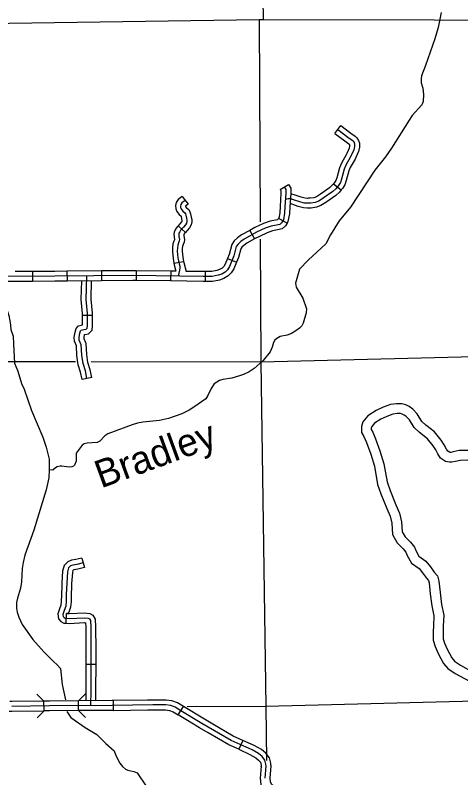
# Model space of a CAD drawing. Extents: x 1373862 to 1376999, y 1168398 to 1170455.
# Drawn here: x 1375274.1 to 1375410.3, y 1169193.7 to 1169426.9 of the extents above; entities that cross this region are included whole.
import ezdxf

# ---------------------------------------------------------------- set-up
doc = ezdxf.new("R2010")
doc.units = 0
for name, color, linetype in [('Level 31', 7, 'Continuous'), ('Level 32', 7, 'Continuous'), ('Level 35', 7, 'Continuous'), ('Level 38', 7, 'Continuous'), ('Level 4', 7, 'Continuous'), ('Level 45', 7, 'Continuous'), ('Level 46', 7, 'Continuous'), ('Level 5', 7, 'Continuous'), ('Level 8', 7, 'Continuous')]:
    doc.layers.add(name, color=color, linetype=linetype)

msp = doc.modelspace()

# ---------------------------------------------------------------- linework, layer by layer
at = {"layer": 'Level 31'}
for p, q in [((1375282.94, 1169214.11), (1375282.9, 1169217.11)), ((1375304.02, 1169217.24), (1375304.06, 1169214.24)), ((1375314.58, 1169217.38), (1375314.58, 1169217.38)), ((1375323.97, 1169212.86), (1375325.52, 1169215.43)), ((1375343.71, 1169205.08), (1375342.47, 1169202.35)), ((1375352.29, 1169197.61), (1375352.29, 1169197.61))]:
    msp.add_line(p, q, dxfattribs=at)
for points in [[(1375282.9, 1169217.11), (1375273.12, 1169216.99), (1375272.43, 1169217.02)], [(1375293.49, 1169214.18), (1375293.47, 1169217.18), (1375284.59, 1169217.13), (1375282.9, 1169217.11)], [(1375304.02, 1169217.24), (1375303.79, 1169217.24), (1375293.47, 1169217.18)], [(1375314.58, 1169217.38), (1375304.02, 1169217.24)], [(1375325.52, 1169215.43), (1375325.51, 1169215.44), (1375323.71, 1169216.55), (1375322.04, 1169217.2), (1375320.29, 1169217.43), (1375316.17, 1169217.41), (1375314.58, 1169217.38)], [(1375350.51, 1169193.53), (1375350.83, 1169197.25), (1375350.74, 1169197.79), (1375350.43, 1169199.06), (1375349.61, 1169200.13), (1375348.51, 1169201.03), (1375346.51, 1169202.16), (1375340.11, 1169205.07), (1375331.19, 1169210.26), (1375324.73, 1169214.16), (1375323.04, 1169215.2), (1375321.66, 1169215.74), (1375320.19, 1169215.93), (1375316.19, 1169215.91), (1375303.8, 1169215.74), (1375284.6, 1169215.63), (1375273.09, 1169215.49)], [(1375304.06, 1169214.24), (1375303.82, 1169214.24), (1375293.49, 1169214.18)], [(1375304.06, 1169214.24), (1375314.62, 1169214.38)], [(1375314.62, 1169214.38), (1375316.2, 1169214.41), (1375320.1, 1169214.43), (1375321.28, 1169214.27), (1375322.37, 1169213.85), (1375323.95, 1169212.88), (1375323.97, 1169212.86)], [(1375334.57, 1169210.03), (1375331.96, 1169211.55), (1375325.52, 1169215.43)], [(1375272.29, 1169214.03), (1375273.07, 1169213.99), (1375282.94, 1169214.11)], [(1375293.49, 1169214.18), (1375284.61, 1169214.13), (1375282.94, 1169214.11)], [(1375333.06, 1169207.44), (1375330.43, 1169208.97), (1375323.97, 1169212.86)], [(1375343.71, 1169205.08), (1375340.79, 1169206.4), (1375334.57, 1169210.03)], [(1375342.47, 1169202.35), (1375339.42, 1169203.74), (1375333.06, 1169207.44)], [(1375352.29, 1169197.61), (1375352.21, 1169198.09), (1375351.81, 1169199.72), (1375350.7, 1169201.18), (1375349.36, 1169202.28), (1375347.19, 1169203.5), (1375343.71, 1169205.08)], [(1375342.47, 1169202.35), (1375345.83, 1169200.82), (1375347.66, 1169199.79), (1375348.52, 1169199.08), (1375349.05, 1169198.4), (1375349.27, 1169197.49), (1375349.33, 1169197.13)], [(1375349.33, 1169197.13), (1375349.32, 1169197.19), (1375349.01, 1169193.51), (1375349.22, 1169191.61), (1375349.88, 1169190.13), (1375350.79, 1169189.05), (1375352.54, 1169187.97), (1375354.46, 1169187.8)], [(1375354.73, 1169190.79), (1375353.51, 1169190.9), (1375352.77, 1169191.35), (1375352.44, 1169191.74), (1375352.15, 1169192.4), (1375352.02, 1169193.55), (1375352.34, 1169197.31), (1375352.29, 1169197.61)]]:
    msp.add_lwpolyline(points, dxfattribs=at)
at = {"layer": 'Level 32'}
for p, q in [((1375355.06, 1169373.58), (1375357.62, 1169375.15)), ((1375325.16, 1169371.45), (1375326.96, 1169369.05)), ((1375354.62, 1169364.78), (1375357.22, 1169363.29)), ((1375323.88, 1169362.46), (1375326.12, 1169360.46)), ((1375345.82, 1169361.06), (1375347.27, 1169358.44)), ((1375338.98, 1169352.45), (1375341.77, 1169351.36)), ((1375322.65, 1169351.01), (1375325.59, 1169351.57)), ((1375279.39, 1169348.48), (1375279.4, 1169345.48)), ((1375289.94, 1169348.55), (1375289.97, 1169345.56)), ((1375300.5, 1169348.65), (1375300.53, 1169345.65)), ((1375311.09, 1169348.73), (1375311.06, 1169345.73)), ((1375321.65, 1169348.6), (1375321.62, 1169345.6)), ((1375332.19, 1169348.48), (1375332.19, 1169345.48))]:
    msp.add_line(p, q, dxfattribs=at)
for points in [[(1375357.62, 1169375.15), (1375358.33, 1169374), (1375358.33, 1169372.39), (1375358.06, 1169368.23), (1375357.97, 1169366.11), (1375357.5, 1169363.78), (1375357.22, 1169363.29)], [(1375356.34, 1169374.37), (1375356.83, 1169373.58), (1375356.83, 1169372.43), (1375356.56, 1169368.31), (1375356.47, 1169366.29), (1375356.08, 1169364.31), (1375355.55, 1169363.39), (1375354.98, 1169362.91), (1375353.97, 1169362.69), (1375352.39, 1169362.38), (1375350.55, 1169361.77), (1375348.05, 1169360.58), (1375344.1, 1169358.39), (1375343.05, 1169357.64), (1375342.22, 1169356.9), (1375341.69, 1169356.11), (1375340.9, 1169353.25), (1375339.63, 1169350.01), (1375339.01, 1169349.04), (1375338.27, 1169348.34), (1375337.26, 1169347.72), (1375336.16, 1169347.33), (1375334.32, 1169346.98), (1375331.56, 1169346.98), (1375310.1, 1169347.24), (1375286.24, 1169347.02), (1375271.54, 1169346.93)], [(1375355.06, 1169373.58), (1375355.33, 1169373.15), (1375355.33, 1169372.48), (1375355.06, 1169368.39), (1375354.98, 1169366.47), (1375354.66, 1169364.85), (1375354.62, 1169364.78)], [(1375325.16, 1169371.45), (1375323.92, 1169370.52), (1375323.29, 1169369.62), (1375323.1, 1169368.64), (1375323.21, 1169367.68), (1375323.54, 1169366.88), (1375324.21, 1169365.97), (1375324.8, 1169365.46), (1375324.82, 1169365.41), (1375324.96, 1169364.57), (1375325.07, 1169364.08), (1375325.07, 1169363.91), (1375325.05, 1169363.8), (1375324.97, 1169363.65), (1375324.43, 1169363.08), (1375323.88, 1169362.46)], [(1375326.06, 1169370.25), (1375325.01, 1169369.46), (1375324.7, 1169369.02), (1375324.61, 1169368.58), (1375324.68, 1169368.06), (1375324.85, 1169367.62), (1375325.32, 1169367), (1375325.97, 1169366.43), (1375326.17, 1169366.1), (1375326.28, 1169365.77), (1375326.43, 1169364.85), (1375326.57, 1169364.24), (1375326.57, 1169363.78), (1375326.48, 1169363.29), (1375326.19, 1169362.77), (1375325.53, 1169362.07), (1375324.77, 1169361.2), (1375324.39, 1169360.65), (1375324.17, 1169360.19), (1375324.15, 1169359.8), (1375324.17, 1169359.23), (1375324.31, 1169358.28), (1375324.26, 1169357.84), (1375324.04, 1169357.23), (1375323.78, 1169356.55), (1375323.69, 1169355.78), (1375323.67, 1169354.71), (1375323.85, 1169352.71), (1375324.2, 1169350.89), (1375324.39, 1169350.13), (1375324.44, 1169349.6), (1375324.35, 1169348.92), (1375323.96, 1169347.07)], [(1375326.96, 1169369.05), (1375326.14, 1169368.44), (1375326.14, 1169368.43), (1375326.17, 1169368.36), (1375326.42, 1169368.03), (1375327.14, 1169367.41), (1375327.54, 1169366.73), (1375327.74, 1169366.14), (1375327.91, 1169365.13), (1375328.07, 1169364.4), (1375328.07, 1169363.64), (1375327.91, 1169362.79), (1375327.42, 1169361.88), (1375326.64, 1169361.05), (1375326.12, 1169360.46)], [(1375354.62, 1169364.78), (1375354.38, 1169364.37), (1375354.3, 1169364.3), (1375353.67, 1169364.16), (1375352.01, 1169363.84), (1375349.99, 1169363.16), (1375347.37, 1169361.92), (1375345.82, 1169361.06)], [(1375323.88, 1169362.46), (1375323.58, 1169362.13), (1375323.09, 1169361.4), (1375322.69, 1169360.57), (1375322.65, 1169359.81), (1375322.68, 1169359.09), (1375322.8, 1169358.25), (1375322.79, 1169358.18), (1375322.64, 1169357.75), (1375322.31, 1169356.91), (1375322.19, 1169355.88), (1375322.17, 1169354.66), (1375322.36, 1169352.5), (1375322.65, 1169351.01)], [(1375357.22, 1169363.29), (1375356.72, 1169362.42), (1375355.67, 1169361.52), (1375354.28, 1169361.22), (1375352.78, 1169360.93), (1375351.11, 1169360.37), (1375348.74, 1169359.25), (1375347.27, 1169358.44)], [(1375326.12, 1169360.46), (1375325.95, 1169360.28), (1375325.7, 1169359.91), (1375325.66, 1169359.82), (1375325.65, 1169359.79), (1375325.67, 1169359.36), (1375325.82, 1169358.31), (1375325.74, 1169357.51), (1375325.45, 1169356.71), (1375325.25, 1169356.19), (1375325.19, 1169355.68), (1375325.17, 1169354.76), (1375325.33, 1169352.92), (1375325.59, 1169351.57)], [(1375345.82, 1169361.06), (1375343.3, 1169359.66), (1375342.11, 1169358.82), (1375341.07, 1169357.89), (1375340.31, 1169356.74), (1375339.48, 1169353.73), (1375338.98, 1169352.45)], [(1375347.27, 1169358.44), (1375344.9, 1169357.12), (1375343.99, 1169356.47), (1375343.36, 1169355.91), (1375343.07, 1169355.47), (1375342.33, 1169352.78), (1375341.77, 1169351.36)], [(1375338.98, 1169352.45), (1375338.28, 1169350.69), (1375337.85, 1169350), (1375337.35, 1169349.54), (1375336.61, 1169349.08), (1375335.77, 1169348.78), (1375334.18, 1169348.48), (1375332.19, 1169348.48)], [(1375322.65, 1169351.01), (1375322.73, 1169350.56), (1375323.25, 1169348.58)], [(1375325.59, 1169351.57), (1375325.66, 1169351.22), (1375326.35, 1169348.54)], [(1375341.77, 1169351.36), (1375340.97, 1169349.32), (1375340.18, 1169348.08), (1375339.18, 1169347.14), (1375337.91, 1169346.36), (1375336.56, 1169345.88), (1375334.46, 1169345.48), (1375332.19, 1169345.48)], [(1375279.39, 1169348.48), (1375274.13, 1169348.45)], [(1375289.94, 1169348.55), (1375286.23, 1169348.52), (1375279.39, 1169348.48)], [(1375300.5, 1169348.65), (1375289.94, 1169348.55)], [(1375311.09, 1169348.73), (1375310.11, 1169348.74), (1375300.5, 1169348.65)], [(1375321.65, 1169348.6), (1375311.09, 1169348.73)], [(1375323.25, 1169348.58), (1375321.65, 1169348.6)], [(1375332.19, 1169348.48), (1375331.57, 1169348.48), (1375326.35, 1169348.54)], [(1375279.4, 1169345.48), (1375271.57, 1169345.43), (1375268.88, 1169345.35)], [(1375289.97, 1169345.56), (1375286.25, 1169345.52), (1375279.4, 1169345.48)], [(1375300.53, 1169345.65), (1375289.97, 1169345.56)], [(1375311.06, 1169345.73), (1375310.1, 1169345.74), (1375300.53, 1169345.65)], [(1375321.62, 1169345.6), (1375311.06, 1169345.73)], [(1375332.19, 1169345.48), (1375331.55, 1169345.48), (1375321.62, 1169345.6)]]:
    msp.add_lwpolyline(points, dxfattribs=at)
at = {"layer": 'Level 35'}
for points in [[(1375404.32, 1169427.73), (1375403.4, 1169423.15), (1375402.39, 1169419.65), (1375399.52, 1169411.53), (1375398.31, 1169408.37), (1375398.19, 1169407.44), (1375398.26, 1169406.24), (1375398.67, 1169404.55), (1375398.88, 1169402.59), (1375398.81, 1169400.5), (1375398.4, 1169399.52), (1375395.49, 1169396.16), (1375394.5, 1169394.75), (1375389.16, 1169386.24), (1375387.29, 1169383.56), (1375384.04, 1169379.52), (1375376.57, 1169368.14), (1375373.1, 1169364), (1375370.53, 1169359.72), (1375369.03, 1169356.97), (1375363.66, 1169351.93), (1375361.03, 1169349.25), (1375359.78, 1169344.9), (1375360.05, 1169343.67), (1375362.04, 1169340.35), (1375363.14, 1169337.09), (1375363.1, 1169335.83), (1375362.12, 1169332.69), (1375361.7, 1169331.88), (1375361.04, 1169331.16), (1375359.94, 1169330.3), (1375358.62, 1169329.53), (1375357.27, 1169329.07), (1375355.12, 1169328.57), (1375354.06, 1169327.98), (1375353.45, 1169327.48), (1375353.07, 1169326.81), (1375352.63, 1169325.31), (1375352.09, 1169323.89)], [(1375268.34, 1169343.59), (1375269.9, 1169341), (1375271.11, 1169338.04), (1375272.15, 1169335.06), (1375272.44, 1169333.45), (1375272.63, 1169332.04), (1375272.76, 1169330.71), (1375273.44, 1169328.67), (1375273.63, 1169326.29), (1375273.94, 1169320.49), (1375274.94, 1169318), (1375276.07, 1169314.23)], [(1375352.09, 1169323.89), (1375349.93, 1169321.27), (1375347.12, 1169318.83), (1375345.64, 1169317.84), (1375343.93, 1169317.02), (1375342.68, 1169316.56), (1375340.29, 1169315.89), (1375337.62, 1169315.48), (1375336.57, 1169315.15), (1375334.94, 1169314.09), (1375333.98, 1169312.72), (1375332.95, 1169310.52), (1375332.4, 1169309.56), (1375328.67, 1169306.96), (1375327.31, 1169306.12), (1375325.04, 1169304.93), (1375320.97, 1169303.52), (1375318.23, 1169302.97), (1375313.14, 1169302.39), (1375311.45, 1169302.06), (1375309.84, 1169301.62), (1375302.47, 1169298.87), (1375301.49, 1169298.2), (1375299.99, 1169296.6), (1375299.12, 1169296.21), (1375296.07, 1169296.03), (1375295.17, 1169295.81), (1375294.6, 1169295.41), (1375292.79, 1169292.96), (1375292.71, 1169290.49), (1375292.24, 1169289.23), (1375291.91, 1169288.98), (1375291.42, 1169288.73), (1375290.6, 1169288.62), (1375288.41, 1169288.93), (1375287.83, 1169288.91), (1375286.94, 1169288.71), (1375286.44, 1169288.45), (1375285.64, 1169287.69), (1375284.54, 1169287.88)], [(1375276.07, 1169314.23), (1375276.83, 1169312.55), (1375279.09, 1169305.95), (1375282.52, 1169297.84), (1375283.6, 1169294.78), (1375284.46, 1169291.07), (1375284.54, 1169287.88), (1375284.42, 1169285.37), (1375283.6, 1169281.68), (1375279.82, 1169269.34), (1375277.08, 1169261.7), (1375276.56, 1169259.5), (1375276.29, 1169257.61), (1375276.01, 1169253.55), (1375275.74, 1169251.65), (1375274.86, 1169248.6), (1375274.56, 1169247.21), (1375274.52, 1169245.54), (1375274.76, 1169244.28), (1375275.2, 1169242.75), (1375276.21, 1169240.55), (1375279.51, 1169235.95), (1375282.83, 1169232.22), (1375285.81, 1169229.23), (1375286.96, 1169228.24), (1375287.93, 1169227.1), (1375288.42, 1169222.15), (1375289.52, 1169217.47)], [(1375289.87, 1169213.89), (1375291.09, 1169212.12), (1375295.47, 1169209.01), (1375299.06, 1169206.85), (1375301.79, 1169204.15), (1375304.41, 1169201.87)], [(1375304.41, 1169201.87), (1375304.78, 1169200.75), (1375305.29, 1169199.64), (1375306.14, 1169198.09), (1375306.91, 1169197.08), (1375307.84, 1169196.31), (1375308.55, 1169195.98), (1375310.39, 1169195.59), (1375311.42, 1169195.16), (1375314.12, 1169191.13), (1375314.2, 1169189.37), (1375314.12, 1169188.15), (1375314.27, 1169186.17), (1375314.52, 1169184.51), (1375315.66, 1169180.56), (1375316.04, 1169179.76)]]:
    msp.add_lwpolyline(points, dxfattribs=at)
at = {"layer": 'Level 38'}
for points in [[(1375280.75, 1169219.2), (1375282.9, 1169217.11)], [(1375293.47, 1169217.18), (1375295.58, 1169219.31)], [(1375282.94, 1169214.11), (1375280.84, 1169211.96)], [(1375295.62, 1169212.07), (1375293.49, 1169214.18)]]:
    msp.add_lwpolyline(points, dxfattribs=at)
at = {"layer": 'Level 4'}
msp.add_lwpolyline([(1375141.28, 1169422.97), (1375218.46, 1169423.68), (1375243.37, 1169424.03), (1375244.34, 1169424.04), (1375348.71, 1169425.54), (1375349.94, 1169425.54), (1375454.46, 1169425.4), (1375455.43, 1169425.4), (1375476.41, 1169425.48)], dxfattribs=at)
at = {"layer": 'Level 45'}
for p, q in [((1375371.82, 1169390.71), (1375373.61, 1169393.12)), ((1375371.44, 1169375.34), (1375373.78, 1169373.47)), ((1375297.7, 1169335.02), (1375294.7, 1169335.02)), ((1375297.49, 1169316.03), (1375294.55, 1169315.47)), ((1375294.47, 1169260.85), (1375295.28, 1169257.97)), ((1375289.69, 1169240.91), (1375289.8, 1169243.91)), ((1375295.72, 1169228.37), (1375298.72, 1169228.36))]:
    msp.add_line(p, q, dxfattribs=at)
for points in [[(1375372.72, 1169391.91), (1375375.79, 1169389.63), (1375377.08, 1169388.71), (1375377.39, 1169388.4), (1375377.68, 1169387.96), (1375377.83, 1169387.46), (1375377.85, 1169386.69), (1375377.59, 1169385.7), (1375376.64, 1169383.55), (1375375.2, 1169380.98), (1375374.71, 1169379.78), (1375373.88, 1169376.73), (1375373.51, 1169375.67), (1375372.94, 1169374.82), (1375372.15, 1169373.83), (1375371.16, 1169372.93), (1375368.27, 1169370.89), (1375366.91, 1169369.99), (1375365.81, 1169369.59), (1375364.45, 1169369.4), (1375363.37, 1169369.37), (1375362.47, 1169369.44), (1375361.07, 1169369.77), (1375359.23, 1169370.45), (1375358.35, 1169370.69), (1375357.53, 1169370.68), (1375356.71, 1169370.54)], [(1375373.61, 1169393.12), (1375376.67, 1169390.84), (1375378.06, 1169389.86), (1375378.56, 1169389.35), (1375379.05, 1169388.6), (1375379.32, 1169387.7), (1375379.36, 1169386.51), (1375379.01, 1169385.2), (1375378.21, 1169383.39)], [(1375371.82, 1169390.71), (1375374.91, 1169388.42), (1375376.11, 1169387.56), (1375376.22, 1169387.45), (1375376.3, 1169387.32), (1375376.34, 1169387.21), (1375376.35, 1169386.86), (1375376.17, 1169386.2), (1375375.46, 1169384.59)], [(1375375.46, 1169384.59), (1375375.3, 1169384.22), (1375373.84, 1169381.63), (1375373.29, 1169380.25), (1375372.45, 1169377.17), (1375372.16, 1169376.35), (1375371.73, 1169375.7), (1375371.44, 1169375.34)], [(1375378.21, 1169383.39), (1375377.99, 1169382.88), (1375376.55, 1169380.33), (1375376.14, 1169379.3), (1375375.31, 1169376.28), (1375374.86, 1169375), (1375374.15, 1169373.93), (1375373.78, 1169373.47)], [(1375371.44, 1169375.34), (1375371.05, 1169374.86), (1375370.22, 1169374.1), (1375367.42, 1169372.13), (1375366.23, 1169371.34), (1375365.44, 1169371.06), (1375364.32, 1169370.89), (1375363.65, 1169370.88)], [(1375373.78, 1169373.47), (1375373.25, 1169372.8), (1375372.1, 1169371.76), (1375369.11, 1169369.65), (1375367.58, 1169368.64), (1375366.17, 1169368.13), (1375364.57, 1169367.9), (1375363.71, 1169367.88)], [(1375363.65, 1169370.88), (1375363.41, 1169370.87), (1375362.7, 1169370.93), (1375361.5, 1169371.21), (1375359.69, 1169371.88), (1375358.32, 1169372.25)], [(1375363.71, 1169367.88), (1375363.33, 1169367.87), (1375362.25, 1169367.95), (1375360.64, 1169368.33), (1375358.13, 1169369.26)], [(1375296.02, 1169315.75), (1375295.58, 1169318.07), (1375294.88, 1169320.31), (1375294.49, 1169322.95), (1375294.31, 1169326.11), (1375293.7, 1169327.51), (1375293.65, 1169328.34), (1375293.87, 1169329.66), (1375294.05, 1169330.32), (1375294.27, 1169330.54), (1375295.06, 1169330.71), (1375295.8, 1169330.85), (1375296.15, 1169331.2), (1375296.2, 1169331.9), (1375296.2, 1169335.67), (1375295.8, 1169339.98), (1375295.98, 1169347.11)], [(1375294.7, 1169335.02), (1375294.7, 1169335.61), (1375294.3, 1169339.93), (1375294.44, 1169345.6)], [(1375297.7, 1169335.02), (1375297.7, 1169335.74), (1375297.3, 1169340.03), (1375297.44, 1169345.62)], [(1375292.83, 1169325.75), (1375292.21, 1169327.16), (1375292.15, 1169328.43), (1375292.4, 1169329.98), (1375292.7, 1169331.1), (1375293.51, 1169331.91), (1375294.7, 1169332.17), (1375294.7, 1169335.02)], [(1375295.68, 1169326.72), (1375295.18, 1169327.86), (1375295.16, 1169328.26), (1375295.32, 1169329.24), (1375295.35, 1169329.24), (1375296.53, 1169329.45), (1375297.61, 1169330.54), (1375297.7, 1169331.85), (1375297.7, 1169335.02)], [(1375297.49, 1169316.03), (1375297.04, 1169318.44), (1375296.35, 1169320.65), (1375295.98, 1169323.1), (1375295.79, 1169326.46), (1375295.68, 1169326.72)], [(1375294.55, 1169315.47), (1375294.12, 1169317.71), (1375293.41, 1169319.97), (1375292.99, 1169322.79), (1375292.83, 1169325.75)], [(1375294.47, 1169260.85), (1375292.68, 1169260.36), (1375291.34, 1169260.17), (1375290.18, 1169259.73), (1375289.05, 1169258.6), (1375288.6, 1169256.88), (1375288.37, 1169253.25), (1375288.33, 1169252.23)], [(1375294.87, 1169259.41), (1375292.99, 1169258.88), (1375291.71, 1169258.71), (1375291.01, 1169258.44), (1375290.4, 1169257.83), (1375290.09, 1169256.64), (1375289.87, 1169253.18), (1375289.74, 1169249.67), (1375289.7, 1169247.52), (1375289.56, 1169246.15), (1375289.08, 1169244.84), (1375288.69, 1169243.61), (1375288.77, 1169242.95), (1375289.04, 1169242.64), (1375289.43, 1169242.42), (1375290.62, 1169242.38), (1375295.31, 1169242.6), (1375296.45, 1169242.47), (1375296.8, 1169242.29), (1375297.11, 1169241.77), (1375297.2, 1169239.83), (1375297.24, 1169233.72), (1375297.2, 1169220.51), (1375297.15, 1169215.7)], [(1375295.28, 1169257.97), (1375293.29, 1169257.41), (1375292.08, 1169257.24), (1375291.84, 1169257.15), (1375291.75, 1169257.06), (1375291.58, 1169256.41), (1375291.37, 1169253.1), (1375291.33, 1169252.12)], [(1375288.33, 1169252.23), (1375288.24, 1169249.71), (1375288.2, 1169247.6), (1375288.09, 1169246.49), (1375287.66, 1169245.33), (1375287.16, 1169243.75), (1375287.35, 1169242.31), (1375288.07, 1169241.46), (1375289.02, 1169240.94), (1375289.69, 1169240.91)], [(1375291.33, 1169252.12), (1375291.24, 1169249.62), (1375291.19, 1169247.43), (1375291.04, 1169245.82), (1375290.5, 1169244.35), (1375290.35, 1169243.89), (1375289.8, 1169243.91)], [(1375289.8, 1169243.91), (1375290.61, 1169243.88), (1375295.36, 1169244.1), (1375296.89, 1169243.93), (1375297.87, 1169243.43), (1375298.59, 1169242.2), (1375298.7, 1169239.87), (1375298.7, 1169238.94)], [(1375289.69, 1169240.91), (1375290.62, 1169240.88), (1375295.26, 1169241.1), (1375295.64, 1169241.05), (1375295.7, 1169239.79), (1375295.7, 1169238.92)], [(1375295.7, 1169238.92), (1375295.74, 1169233.72), (1375295.72, 1169228.37)], [(1375298.7, 1169238.94), (1375298.74, 1169233.72), (1375298.72, 1169228.36)], [(1375295.72, 1169228.37), (1375295.7, 1169220.52), (1375295.67, 1169217.82)], [(1375298.72, 1169228.36), (1375298.7, 1169220.5), (1375298.67, 1169217.79)], [(1375295.67, 1169217.82), (1375295.67, 1169217.19)], [(1375298.67, 1169217.79), (1375298.67, 1169217.21)]]:
    msp.add_lwpolyline(points, dxfattribs=at)
at = {"layer": 'Level 46'}
for points in [[(1375412.55, 1169293.79), (1375409.78, 1169293.72), (1375408.04, 1169293.3), (1375407.31, 1169293.14), (1375407.09, 1169293.14), (1375406.83, 1169293.19), (1375406.33, 1169293.53), (1375405.95, 1169294.17), (1375405.28, 1169295.5), (1375404.29, 1169296.92), (1375402.27, 1169299.49), (1375399.62, 1169301.48), (1375398.46, 1169302.64), (1375397, 1169304.93), (1375395.64, 1169306.44), (1375394.55, 1169307.2), (1375393.5, 1169307.68), (1375392.35, 1169308.04), (1375390.68, 1169308.04), (1375388.87, 1169307.81), (1375386.59, 1169306.96), (1375384.46, 1169305.99), (1375381.91, 1169304.39), (1375380.42, 1169302.56), (1375379.93, 1169301.1), (1375379.93, 1169299.27), (1375380.73, 1169297.99), (1375381.45, 1169296.19), (1375382.78, 1169292.64), (1375383.9, 1169288.97), (1375384.87, 1169283.39), (1375385.89, 1169280.47), (1375387.72, 1169275.96), (1375388.76, 1169273.63), (1375389.22, 1169271.56), (1375389.43, 1169268.04), (1375390.86, 1169265.5), (1375392.68, 1169263.67), (1375393.53, 1169262.61), (1375393.93, 1169261.63), (1375395.25, 1169259.31), (1375397.6, 1169257.7), (1375398.66, 1169256.35), (1375399.83, 1169254.74), (1375400.43, 1169253.98), (1375400.64, 1169253.23), (1375401.01, 1169249.92), (1375401.47, 1169246.2), (1375402.09, 1169243.16), (1375401.97, 1169240.12), (1375401.91, 1169238.35), (1375401.91, 1169235.7), (1375402.51, 1169233.8), (1375403.41, 1169231.67), (1375405.06, 1169228.63), (1375406.38, 1169227.08), (1375408.61, 1169225.5), (1375412.96, 1169223.15)], [(1375412.44, 1169290.78), (1375410.18, 1169290.72), (1375408.7, 1169290.37), (1375407.63, 1169290.14), (1375406.82, 1169290.14), (1375405.66, 1169290.35), (1375404.09, 1169291.43), (1375403.32, 1169292.72), (1375402.69, 1169293.97), (1375401.88, 1169295.13), (1375400.16, 1169297.33), (1375397.65, 1169299.21), (1375396.11, 1169300.75), (1375394.6, 1169303.11), (1375393.64, 1169304.18), (1375393.06, 1169304.58), (1375392.43, 1169304.87), (1375391.9, 1169305.04), (1375390.87, 1169305.04), (1375389.59, 1169304.88), (1375387.74, 1169304.18), (1375385.88, 1169303.34), (1375383.92, 1169302.11), (1375383.09, 1169301.09), (1375382.93, 1169300.62), (1375382.93, 1169300.13), (1375383.42, 1169299.35), (1375384.25, 1169297.28), (1375385.62, 1169293.61), (1375386.82, 1169289.67), (1375387.78, 1169284.15), (1375388.7, 1169281.53), (1375390.48, 1169277.14), (1375391.63, 1169274.57), (1375392.2, 1169271.97), (1375392.38, 1169268.91), (1375393.27, 1169267.33), (1375394.92, 1169265.68), (1375396.14, 1169264.15), (1375396.64, 1169262.95), (1375397.52, 1169261.39), (1375399.67, 1169259.91), (1375401.06, 1169258.16), (1375402.22, 1169256.55), (1375403.16, 1169255.38), (1375403.59, 1169253.8), (1375403.99, 1169250.28), (1375404.44, 1169246.69), (1375405.11, 1169243.41), (1375404.97, 1169240), (1375404.91, 1169238.29), (1375404.91, 1169236.17), (1375405.33, 1169234.84), (1375406.11, 1169232.97), (1375407.55, 1169230.34), (1375408.42, 1169229.31), (1375410.19, 1169228.05), (1375414.21, 1169225.89)]]:
    msp.add_lwpolyline(points, dxfattribs=at)
at = {"layer": 'Level 5'}
for points in [[(1375348.25, 1169528.62), (1375349.94, 1169425.54)], [(1375348.71, 1169425.54), (1375348.98, 1169363.71)], [(1375349, 1169358.37), (1375349.17, 1169320.78)], [(1375426.72, 1169322.73), (1375349.17, 1169320.78)], [(1375292.58, 1169320.88), (1375268.2, 1169320.91)], [(1375349.17, 1169320.78), (1375297.38, 1169320.87)], [(1375349.17, 1169320.78), (1375350.76, 1169215.42)], [(1375350.76, 1169215.42), (1375350.92, 1169198.98)]]:
    msp.add_lwpolyline(points, dxfattribs=at)
at = {"layer": 'Level 8'}
msp.add_lwpolyline([(1375426.88, 1169217.4), (1375350.76, 1169215.42), (1375326.66, 1169215.33)], dxfattribs=at)

# ---------------------------------------------------------------- texts
at = {"layer": 'Level 35'}
msp.add_text('Bradley', height=8.448, rotation=20.1115, dxfattribs=at).set_placement((1375300.34, 1169282.11))

doc.saveas('drawing.dxf')
